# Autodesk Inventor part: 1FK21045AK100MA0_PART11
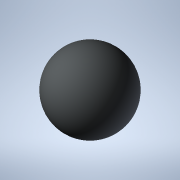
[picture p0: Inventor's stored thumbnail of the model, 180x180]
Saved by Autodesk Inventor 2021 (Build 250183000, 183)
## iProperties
Created: 2025-04
Part Number: 1FK21045AK100MA0_PART11
Material: Generic
Catalog Web Link: www.3dfindit.com
Description: -Servo synchronous motor
Document SubType Name: Modeling
Designer: psAdmin
Mass: 0.137258 g
Surface Area: 1.2868 cm^2
Volume: 0.137258 cm^3
Density: 1 g/cm^3
Appearance: PSOLRGB-212-217-219
Category: PARTsolutions
Title: 1FK21045AK100MA0_PART11
Author: Cadenas PARTsolutions
Comments: Servo synchronous motor
Sending System: PARTsolutions
Preprocessor: ST-DEVELOPER v19.3
PSOL_IDENT_0: {$CADENAS_DATA/23d-libs/siemens_ag/_cat_/e0/5f/1fk21045ak100ma0.prj},216 {VTYP=3D},{NB=1FK21045AK100
PSOL_IDENT_1: MA0_PART11},{LINA=1FK21045AK100MA0_PART11},{NN=1FK21045AK100MA0_PART11},{NOPRJ=TRUE},{DATE=19.08.202
PSOL_IDENT_2: 5 14:01:03},{GEOMDATE=30.07.2025 02:01:57},{VERSION=},{LINEID=10},{WBVAR=},{WBNUMERIC=}  {NB=1FK2104
PSOL_IDENT_3: 5AK100MA0_PART11},{LINA=1FK21045AK100MA0_PART11},{KT=DUMMY},{PREVIEW=../../../_pool_/0f/2c/p_d211_xx
PSOL_IDENT_4: _00438j.png},{DESCSHORT=SIMOTICS S-1FK2 HD, SINAMICS S210 3AC 400V-480V, 1.7 Nm, 6000 rpm},{DESCLONG=
PSOL_IDENT_5: SIMOTICS S-1FK2 HD servo motor M0=2.4 Nm; PN = 1.07 kW at nN=6000 rpm (380-480 V); PN = 0.75 kW at n
PSOL_IDENT_6: N=3000 rpm (200-240 V); with holding brake; degree of protection IP64; cylindrical shaft D19x40mm; a
PSOL_IDENT_7: bsolute encoder 22-bit + 12-bit multiturn (encoder AM22DQC); with OCC interface; plug size M17, rota
PSOL_IDENT_8: table; SIMOTICS S-1FK2 servomotorfor a wide range of uses in industrial environments. SIMOTICS S‑1FK
PSOL_IDENT_9: 2 servomotors are compact synchronous motors with a high dynamic performance that set themselves apa
PSOL_IDENT_10: rt as a result of their high power density, degree of protection and overload capability. The motors
PSOL_IDENT_11: are available in two variants: as High Dynamic variant (highest dynamic performance as a result of
PSOL_IDENT_12: the low intrinsic moment of inertia for applications demanding a high dynamic performance with low m
PSOL_IDENT_13: oved masses) - and as Compact variant (precise and stable closed-loop control for medium up to large
PSOL_IDENT_14: moved masses as a result of a medium intrinsic moment of inertia). SIMOTICSS‑1FK2 servomotors fully
PSOL_IDENT_15: exploit their strengths in a system with the SINAMICSS210 frequency converter and simple connection
PSOL_IDENT_16: using the one cable connection (OCC). Advantages include the short control and positioning times, f
PSOL_IDENT_17: ast and precise correction of disturbing quantities as well as stable control with a high dynamic pe
PSOL_IDENT_18: rformance. The servo motors can be configured to address a wide range of requirements. For example w
PSOL_IDENT_19: ith and without holding brake, IP64 or IP65 degree of protection, singleturn or multiturn absolute e
PSOL_IDENT_20: ncoders - to name just a few. Further, the servomotors are available in different shaft heights exte
PSOL_IDENT_21: nding from 20 to 100. A shaft sealing ring is available to achieve an IP65 degree of protection and
PSOL_IDENT_22: for subsequent mounting at the motor or as spare part. SIMOTICS - the optimum motor for each and eve
PSOL_IDENT_23: ry motion control application.},{INTNO=804766807114},{SUPPLIERALTNO=1FK2104-5AK10-0MA0},{MANUID=1FK2
PSOL_IDENT_24: 1045AK100MA0},{MANUNAME=Siemens},{MANUTYPEDESC=Synchronous motor 1FK2-HD 2,39 Nm},{AAU732=SIMOTICS},
PSOL_IDENT_25: {AAO057=S-1FK2},{AAU734=SIMOTICS S-1FK2 HD servo motor M0=2.4 Nm; PN = 1.07 kW at nN=6000 rpm (380-4
PSOL_IDENT_26: 80 V); PN = 0.75 kW at nN=3000 rpm (200-240 V); with holding brake; degree of protection IP64; cylin
PSOL_IDENT_27: drical shaft D19x40mm; absolute encoder 22-bit + 12-bit multiturn (encoder AM22DQC); with OCC interf
PSOL_IDENT_28: ace; plug size M17, rotatable;},{AAW338=Synchronous motor 1FK2-HD 2,39 Nm},{AAO742=SIMOTICS},{AAO663=
PSOL_IDENT_29: 4042948691236},{NOCUPEROU=1},{PRICEQUANTITY=1},{QUANTITYMIN=1},{QUANTITYINT=1},{CTN=85015100},{COO=D
PSOL_IDENT_30: E},{AAO676=1FK2104-5AK10-0MA0},{AAO677=Siemens AG},{ORDERUNIT=C62},{CONTENTUNIT=C62}
NB: 1FK21045AK100MA0_PART11
NT: Servo synchronous motor
NBSYN: $MANUID._PART11
LINA: 1FK21045AK100MA0_PART11
CATALOG: SIEMENS
PREVIEW: ../../../_pool_/0f/2c/p_d211_xx_00438j.png
DESCSHORT: SIMOTICS S-1FK2 HD, SINAMICS S210 3AC 400V-480V, 1.7 Nm, 6000 rpm
DESCLONG: SIMOTICS S-1FK2 HD servo motor M0=2.4 Nm; PN = 1.07 kW at nN=6000 rpm (380-480 V); PN = 0.75 kW at nN=3000 rpm (200-240 V); with holding brake; degree of protec
INTNO: 804766807114
SUPPLIERALTNO: 1FK2104-5AK10-0MA0
MANUID: 1FK21045AK100MA0
MANUNAME: Siemens
MANUTYPEDESC: Synchronous motor 1FK2-HD 2,39 Nm
AAU732: SIMOTICS
AAO057: S-1FK2
AAU734: SIMOTICS S-1FK2 HD servo motor M0=2.4 Nm; PN = 1.07 kW at nN=6000 rpm (380-480 V); PN = 0.75 kW at nN=3000 rpm (200-240 V); with holding brake; degree of protec
AAW338: Synchronous motor 1FK2-HD 2,39 Nm
AAO742: SIMOTICS
AAO663: 4042948691236.0
NOCUPEROU: 1
PRICEQUANTITY: 1
QUANTITYMIN: 1
QUANTITYINT: 1
CTN: 85015100
COO: DE
ARTICLENO: 1FK21045AK100MA0_PART11
BOMINFO: 1FK21045AK100MA0_PART11
CREATOR: CADENAS GmbH
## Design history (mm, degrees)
feature "2025_04_17_15_45_15_0090"
body "Solid1"
